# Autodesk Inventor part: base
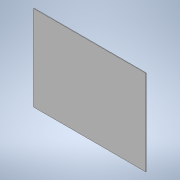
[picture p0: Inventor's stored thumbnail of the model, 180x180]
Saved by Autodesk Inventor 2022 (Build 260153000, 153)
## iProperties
Created: 2021-07
Part Number: base
Material: Generic
Document SubType Name: Modeling
Designer: 91876
Density: 1 g/cm^3
Appearance: Default
Author: 91876
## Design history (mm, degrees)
sketch "Sketch1"
  geometry: L1 (0, 0)-(10500, 0); L2 (10500, 0)-(10500, 8000); L3 (10500, 8000)-(0, 8000); L4 (0, 8000)-(0, 0)
  constraints: 8 end point, 2 parallel, 1 horizontal, 1 perpendicular
  dimensions: "d0" = 10500 distance of L3.end L2.end; "d1" = 8000 distance of L1.end L2.end
extrude "Extrusion1" new body sketch "Sketch1" distance "d2" = 50; taper "d3" = 0 deg
body "Solid1"
